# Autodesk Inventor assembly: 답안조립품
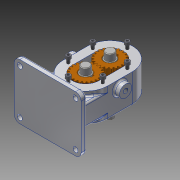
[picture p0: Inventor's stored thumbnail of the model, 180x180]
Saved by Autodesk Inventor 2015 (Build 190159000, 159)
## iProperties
Created: 2020-09
Part Number: 답안조립품
Document SubType Name: Assembly
Designer: LINEART-SSD.D4.16.04
Author: LINEART-SSD.D4.16.04
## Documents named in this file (11)
- C:\Users\LINEART-SSD.D4.16.04\Desktop\700906V1027\답안조립품.iam
- C:\Users\LINEART-SSD.D4.16.04\Desktop\700906V1027\본체.ipt
- C:\Users\LINEART-SSD.D4.16.04\Desktop\700906V1027\메인축.ipt
- C:\Users\LINEART-SSD.D4.16.04\Desktop\700906V1027\키 6 x 6 x 18.ipt
- C:\Users\LINEART-SSD.D4.16.04\Desktop\700906V1027\스퍼기어.ipt
- C:\Users\LINEART-SSD.D4.16.04\Desktop\700906V1027\베어링부시.ipt
- C:\Users\LINEART-SSD.D4.16.04\Desktop\700906V1027\서브축.ipt
- C:\Users\LINEART-SSD.D4.16.04\Desktop\700906V1027\개스킷.ipt
- C:\Users\LINEART-SSD.D4.16.04\Desktop\700906V1027\커버.ipt
- C:\Users\LINEART-SSD.D4.16.04\Desktop\700906V1027\오일 실 16 28 7.ipt
- C:\Users\LINEART-SSD.D4.16.04\Desktop\700906V1027\볼트 M5.ipt
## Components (1 placed, 1 different names)
1. 개스킷:1
